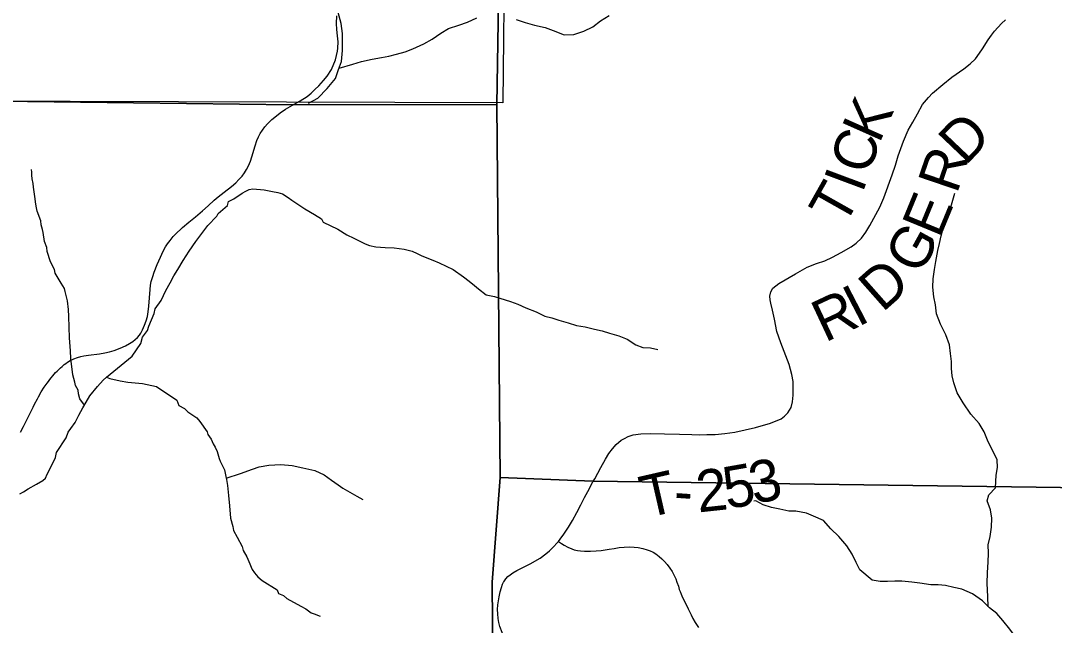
# Model space of a CAD drawing. Extents: x 0 to 34, y -8.9 to 22.
# Drawn here: x 27.543 to 28.944, y 16.605 to 17.424 of the extents above; entities that cross this region are included whole.
import ezdxf

# ---------------------------------------------------------------- set-up
doc = ezdxf.new("R2010")
doc.units = 0
for name, color, linetype in [('GM_X_Corporation', 7, 'Continuous'), ('GM_X_Minor_River', 7, 'Continuous'), ('GM_X_Township_Road', 7, 'Continuous'), ('GM_X_Township_Road_Text', 7, 'Continuous')]:
    doc.layers.add(name, color=color, linetype=linetype)

msp = doc.modelspace()

# ---------------------------------------------------------------- linework, layer by layer
at = {"layer": 'GM_X_Corporation'}
for points in [[(30.5167, 16.7663), (30.5167, 21.4), (28.2203, 21.4), (28.2198, 21.3092), (28.2124, 18.7899), (28.2124, 18.7889), (28.2011, 18.1006), (28.201, 18.0921), (28.1882, 17.3108), (28.1928, 16.8054), (28.3182, 16.8002), (29.5528, 16.7835), (30.4571, 16.7673)], [(28.2049, 18.3054), (28.2008, 17.7487), (28.1963, 17.3129), (27.17, 17.3161), (27.198, 18.314)], [(23.7167, 15.9913), (23.7167, 14.6), (28.1739, 14.6), (28.1809, 15.2987), (28.1918, 16.1509), (28.1846, 16.3341), (28.1817, 16.6637), (28.1928, 16.8054), (28.1882, 17.3108), (27.911, 17.3104), (27.4798, 17.3159), (27.0561, 17.3117), (26.7292, 17.3169), (26.394, 17.3229), (26.1361, 17.3278), (26.135, 17.3055), (26.1186, 15.9366), (25.7922, 15.939), (25.6785, 15.9418), (24.8268, 15.964), (24.2771, 15.9807), (24.0651, 15.9828)], [(28.1739, 14.6), (30.5167, 14.6), (30.5167, 16.7663), (30.4571, 16.7673), (29.5528, 16.7835), (28.3182, 16.8002), (28.1928, 16.8054), (28.1817, 16.6637), (28.1846, 16.3341), (28.1918, 16.1509), (28.1809, 15.2987)]]:
    msp.add_lwpolyline(points, close=True, dxfattribs=at)
for points in [[(26.1391, 17.8847), (26.1361, 17.3278), (26.394, 17.3229), (26.7292, 17.3169), (27.0561, 17.3117), (27.4798, 17.3159), (27.911, 17.3104), (28.1882, 17.3108), (28.201, 18.0921)], [(29.5528, 16.7835), (28.3182, 16.8002), (28.1928, 16.8054), (28.1882, 17.3108), (27.911, 17.3104), (27.4798, 17.3159), (27.0561, 17.3117), (26.7292, 17.3169), (26.394, 17.3229), (26.1361, 17.3278), (26.1391, 17.8847)], [(26.1391, 17.8847), (26.1361, 17.3278), (26.394, 17.3229), (26.7292, 17.3169), (27.0561, 17.3117), (27.4798, 17.3159), (27.911, 17.3104), (28.1882, 17.3108), (28.1928, 16.8054), (28.3182, 16.8002), (29.5528, 16.7835)]]:
    msp.add_lwpolyline(points, dxfattribs=at)
at = {"layer": 'GM_X_Minor_River'}
for points in [[(27.9331, 17.3125), (27.9454, 17.3194), (27.9581, 17.3325), (27.9693, 17.3459), (27.9737, 17.3582), (27.9777, 17.3688), (27.9791, 17.384), (27.9788, 17.4068), (27.9771, 17.4205), (27.9731, 17.4356)], [(28.2145, 17.4258), (28.2267, 17.4218), (28.2393, 17.4182), (28.2537, 17.4149), (28.2644, 17.4109), (28.2793, 17.405), (28.2925, 17.4056), (28.3061, 17.4103), (28.3182, 17.4162), (28.3287, 17.4243), (28.3404, 17.4313)], [(27.9745, 17.3602), (27.993, 17.3652), (28.0047, 17.3688), (28.0194, 17.372), (28.0319, 17.3745), (28.0418, 17.3761), (28.0523, 17.3789), (28.0641, 17.3821), (28.0743, 17.386), (28.0893, 17.3931), (28.1006, 17.3993), (28.1123, 17.4074), (28.1225, 17.4136), (28.1368, 17.4184), (28.1485, 17.4223), (28.161, 17.4282)], [(27.6291, 16.9033), (27.6229, 16.912), (27.6213, 16.9188), (27.6205, 16.9237), (27.6169, 16.9301), (27.6161, 16.9346), (27.6133, 16.9444), (27.6106, 16.9668), (27.6101, 16.977), (27.609, 16.9944), (27.6081, 17.0236), (27.6076, 17.033), (27.6062, 17.0447), (27.603, 17.0572), (27.6022, 17.0613), (27.5975, 17.0685), (27.5897, 17.082), (27.5885, 17.0872), (27.583, 17.0974), (27.5789, 17.1117), (27.5781, 17.117), (27.5753, 17.1249), (27.5732, 17.1374), (27.5724, 17.1412), (27.5704, 17.1476), (27.5699, 17.1532), (27.5651, 17.1664), (27.5639, 17.1732), (27.563, 17.1789), (27.5625, 17.183), (27.56, 17.1989), (27.5595, 17.2038), (27.5583, 17.2099), (27.5578, 17.2152), (27.5578, 17.219), (27.5573, 17.2227)], [(27.6601, 16.9409), (27.6592, 16.9411), (27.6939, 16.9698), (27.7057, 16.9867), (27.7078, 16.9954), (27.7145, 17.0046), (27.7163, 17.0104), (27.7239, 17.0275), (27.725, 17.034), (27.7331, 17.0451), (27.7397, 17.0589), (27.7452, 17.0689), (27.7503, 17.0784), (27.7559, 17.0872), (27.7632, 17.0995), (27.771, 17.1118), (27.7802, 17.1252), (27.7869, 17.134), (27.7965, 17.1467), (27.8088, 17.1595), (27.8106, 17.1629), (27.8229, 17.1737), (27.8243, 17.1794), (27.8315, 17.183), (27.8431, 17.1904), (27.8479, 17.1931), (27.8525, 17.1955), (27.8574, 17.1963), (27.8729, 17.1951), (27.8839, 17.193), (27.8912, 17.1916), (27.8976, 17.1895), (27.9053, 17.1847), (27.9103, 17.181), (27.9279, 17.1696), (27.9409, 17.1615), (27.9505, 17.1556), (27.9528, 17.1515), (27.9727, 17.142), (27.9849, 17.1342), (27.9945, 17.1295), (28.0018, 17.1258), (28.0098, 17.1218), (28.0155, 17.1196), (28.0242, 17.1179), (28.0367, 17.117), (28.0489, 17.1164), (28.0625, 17.1148), (28.0732, 17.1119), (28.0804, 17.1087), (28.0858, 17.1061), (28.0934, 17.1028), (28.1014, 17.0996), (28.1098, 17.0963), (28.1194, 17.0919), (28.1289, 17.0872), (28.1431, 17.0772), (28.1508, 17.0713), (28.1577, 17.0657), (28.1635, 17.0609), (28.1738, 17.0527), (28.1807, 17.0514), (28.1852, 17.0505)], [(28.8641, 16.7912), (28.8649, 16.8085), (28.8667, 16.8191), (28.8662, 16.8294), (28.8595, 16.8433), (28.8541, 16.8535), (28.8486, 16.8671), (28.842, 16.8784), (28.8305, 16.8912), (28.82, 16.9066), (28.8123, 16.9202), (28.8075, 16.9334), (28.8051, 16.9433), (28.8042, 16.9531), (28.8045, 16.9626), (28.8032, 16.9732), (28.8015, 16.985), (28.7968, 16.9986), (28.7894, 17.0129), (28.7843, 17.0269), (28.7826, 17.0394), (28.7806, 17.05), (28.7793, 17.0633), (28.7795, 17.0747), (28.7812, 17.0872), (28.783, 17.0979), (28.7858, 17.1131), (28.788, 17.1226), (28.7905, 17.1326), (28.7941, 17.1463), (28.7981, 17.1577), (28.8025, 17.1684), (28.8055, 17.1779), (28.8091, 17.1905)], [(28.1852, 17.0505), (28.2066, 17.0437), (28.2165, 17.0401), (28.2276, 17.0353), (28.2417, 17.0298), (28.2532, 17.0238), (28.2627, 17.0217), (28.2722, 17.0184), (28.2848, 17.0147), (28.2962, 17.0115), (28.308, 17.0094), (28.3205, 17.0065), (28.3308, 17.004), (28.3407, 17.001), (28.3537, 16.9974), (28.3647, 16.9926), (28.3766, 16.9852), (28.3861, 16.9815), (28.3964, 16.9809), (28.4063, 16.9787)], [(27.5418, 16.7832), (27.5467, 16.786), (27.5531, 16.7899), (27.5643, 16.7965), (27.573, 16.8012), (27.5763, 16.8043), (27.5789, 16.81), (27.5836, 16.8192), (27.5898, 16.8326), (27.5912, 16.8394), (27.6045, 16.859), (27.6071, 16.8666), (27.6108, 16.8716), (27.6167, 16.8797), (27.6214, 16.89), (27.6269, 16.8996), (27.6317, 16.9076), (27.6365, 16.9161), (27.6469, 16.9288), (27.6547, 16.9372), (27.6592, 16.9411), (27.6637, 16.9397), (27.6778, 16.9365), (27.6881, 16.9344), (27.7078, 16.9325), (27.7268, 16.9287), (27.7544, 16.9099), (27.7572, 16.9031), (27.7648, 16.8987), (27.7694, 16.8942), (27.7817, 16.8861), (27.7856, 16.8812), (27.7957, 16.8674), (27.7965, 16.8636), (27.8008, 16.8573), (27.8039, 16.8509), (27.8062, 16.8464), (27.809, 16.8407), (27.8118, 16.8313), (27.8134, 16.8275), (27.8189, 16.8155), (27.8209, 16.8065), (27.8218, 16.8027), (27.8231, 16.7944), (27.8244, 16.7811), (27.8258, 16.7668), (27.8272, 16.7501), (27.8305, 16.7388), (27.8313, 16.7335), (27.8364, 16.7245), (27.843, 16.7117), (27.8443, 16.7065), (27.8493, 16.6978), (27.8533, 16.6884), (27.8553, 16.6839), (27.8565, 16.6805), (27.8599, 16.676), (27.8642, 16.6708), (27.87, 16.6656), (27.8903, 16.6531), (27.8922, 16.6482), (27.8991, 16.6453), (27.9037, 16.6412), (27.9225, 16.6309), (27.9293, 16.6273), (27.9366, 16.6221), (27.9408, 16.6207), (27.9485, 16.6174)], [(27.8214, 16.8044), (27.8409, 16.8106), (27.8571, 16.8166), (27.8662, 16.8198), (27.879, 16.8219), (27.8953, 16.823), (27.9108, 16.8214), (27.9253, 16.8186), (27.9416, 16.8147), (27.9542, 16.8089), (27.9642, 16.8019), (27.973, 16.7956), (27.9795, 16.7908), (27.9983, 16.7801), (28.0067, 16.7753)], [(28.8543, 16.6303), (28.8536, 16.6443), (28.8529, 16.6618), (28.8531, 16.6766), (28.8541, 16.6906), (28.8546, 16.7028), (28.8543, 16.7142), (28.8567, 16.7255), (28.8584, 16.738), (28.8589, 16.7502), (28.8571, 16.7617), (28.8527, 16.7736), (28.8552, 16.7817), (28.8641, 16.7912)], [(28.7763, 16.6601), (28.7616, 16.6623), (28.7506, 16.6635), (28.7373, 16.6649), (28.7278, 16.6649), (28.7175, 16.6642), (28.7076, 16.6642), (28.697, 16.6662), (28.6801, 16.6803), (28.6752, 16.69), (28.6696, 16.7016), (28.6625, 16.7126), (28.6516, 16.7252), (28.641, 16.736), (28.6308, 16.7471), (28.6174, 16.753), (28.6077, 16.7568), (28.5933, 16.7597), (28.5838, 16.7597), (28.5718, 16.7625), (28.5604, 16.7645), (28.5492, 16.7685), (28.5391, 16.7735), (28.5364, 16.7732)], [(28.9478, 16.4515), (28.9393, 16.4652), (28.9305, 16.4823), (28.9275, 16.4935), (28.9261, 16.5053), (28.9244, 16.5179), (28.9206, 16.5284), (28.9147, 16.5404), (28.9098, 16.5517), (28.9051, 16.5652), (28.8977, 16.58), (28.8909, 16.5898), (28.8834, 16.6), (28.8739, 16.6114), (28.866, 16.6209), (28.8557, 16.6289), (28.8462, 16.6381), (28.8329, 16.6478), (28.8183, 16.6538), (28.8077, 16.6565), (28.7964, 16.6589), (28.7862, 16.6597), (28.7763, 16.6601)]]:
    msp.add_lwpolyline(points, dxfattribs=at)
at = {"layer": 'GM_X_Township_Road'}
for points in [[(27.9112, 17.3099), (27.9215, 17.3157), (27.9311, 17.3218), (27.9365, 17.326), (27.9417, 17.3309), (27.9468, 17.3361), (27.9531, 17.3433), (27.958, 17.3491), (27.9641, 17.3582), (27.9695, 17.3711), (27.9722, 17.3828), (27.9727, 17.3869), (27.9731, 17.3956), (27.9724, 17.4036), (27.9711, 17.4122), (27.9707, 17.4207), (27.9712, 17.4307)], [(28.3184, 16.7996), (28.321, 16.8035), (28.329, 16.8189), (28.3354, 16.8304), (28.3399, 16.8378), (28.3449, 16.8443), (28.3501, 16.85), (28.3568, 16.8557), (28.3613, 16.8584), (28.366, 16.8608), (28.3731, 16.863), (28.3835, 16.8647), (28.397, 16.8651), (28.4155, 16.8644), (28.4359, 16.8642), (28.4526, 16.8634), (28.4635, 16.8632), (28.473, 16.8634), (28.484, 16.8637), (28.497, 16.8651), (28.5107, 16.8669), (28.5248, 16.87), (28.5389, 16.8732), (28.5592, 16.8788), (28.5734, 16.8847), (28.5781, 16.8883), (28.5824, 16.8928), (28.5871, 16.9), (28.5889, 16.9078), (28.5898, 16.9169), (28.5898, 16.9249), (28.5896, 16.9354), (28.5882, 16.9447), (28.5843, 16.9586), (28.5732, 16.9876), (28.5678, 17.003), (28.5645, 17.02), (28.5618, 17.032), (28.5595, 17.0415), (28.5586, 17.0461), (28.5581, 17.0511), (28.5594, 17.0568), (28.5621, 17.0618), (28.5702, 17.068), (28.593, 17.0815), (28.609, 17.0902), (28.6216, 17.0951), (28.6325, 17.0991), (28.6431, 17.1039), (28.6549, 17.1102), (28.6682, 17.1177), (28.6753, 17.1229), (28.6822, 17.1297), (28.6881, 17.1376), (28.6938, 17.1469), (28.7073, 17.1716), (28.7126, 17.1845), (28.7238, 17.2153), (28.7286, 17.2286), (28.7322, 17.2414), (28.7392, 17.2611), (28.7458, 17.2759), (28.7518, 17.2869), (28.7581, 17.298), (28.7649, 17.3107), (28.7731, 17.3204), (28.7788, 17.3261), (28.7927, 17.338), (28.8049, 17.3476), (28.8209, 17.3589), (28.8295, 17.3658), (28.8368, 17.3728), (28.8424, 17.3802), (28.8466, 17.3863), (28.8541, 17.3984), (28.8584, 17.4049), (28.8626, 17.4103), (28.872, 17.4206), (28.8777, 17.4253)], [(27.5427, 16.8667), (27.5466, 16.8743), (27.55, 16.8809), (27.5595, 16.9005), (27.5617, 16.9049), (27.5654, 16.9121), (27.5669, 16.9148), (27.5706, 16.9213), (27.5746, 16.9276), (27.5786, 16.9331), (27.5804, 16.9356), (27.5822, 16.9381), (27.584, 16.9404), (27.5865, 16.9433), (27.5883, 16.9455), (27.5902, 16.9474), (27.5923, 16.9495), (27.5944, 16.9518), (27.5967, 16.9538), (27.599, 16.9559), (27.6018, 16.9583), (27.6038, 16.9598), (27.6062, 16.9616), (27.61, 16.9637), (27.615, 16.9662), (27.6196, 16.968), (27.6244, 16.9695), (27.6286, 16.9704), (27.6348, 16.9713), (27.6496, 16.973), (27.6569, 16.9742), (27.663, 16.9757), (27.6695, 16.9776), (27.6776, 16.9807), (27.685, 16.9839), (27.6905, 16.9868), (27.6947, 16.9895), (27.6981, 16.9921), (27.7013, 16.9952), (27.7037, 16.998), (27.7058, 17.0011), (27.7081, 17.0055), (27.7108, 17.0117), (27.7129, 17.0176), (27.7145, 17.0236), (27.7156, 17.0296), (27.7166, 17.0377), (27.7174, 17.0488), (27.7181, 17.06), (27.7189, 17.0661), (27.7198, 17.071), (27.7217, 17.0776), (27.7236, 17.0834), (27.7277, 17.0938), (27.7321, 17.1041), (27.7358, 17.1119), (27.7392, 17.1179), (27.7419, 17.1221), (27.7453, 17.1265), (27.7497, 17.1317), (27.7544, 17.1367), (27.7597, 17.1419), (27.762, 17.144), (27.7705, 17.1511), (27.7798, 17.1584), (27.7892, 17.1665), (27.797, 17.1736), (27.8052, 17.1812), (27.8104, 17.1856), (27.8187, 17.1921), (27.8286, 17.1997), (27.8342, 17.2045), (27.8387, 17.2089), (27.8428, 17.2136), (27.8461, 17.2181), (27.849, 17.2228), (27.8515, 17.2278), (27.8541, 17.2341), (27.8561, 17.24), (27.8604, 17.2549), (27.8628, 17.2619), (27.865, 17.2671), (27.8674, 17.2715), (27.8704, 17.2761), (27.8738, 17.2806), (27.8775, 17.2847), (27.8834, 17.2903), (27.8895, 17.2956), (27.8944, 17.2994), (27.9016, 17.3043), (27.9112, 17.3099)], [(28.2717, 16.7188), (28.2742, 16.7219), (28.279, 16.7284), (28.2854, 16.7381), (28.2908, 16.747), (28.2968, 16.7577), (28.3021, 16.7681), (28.3071, 16.7781), (28.3113, 16.7864), (28.3184, 16.7996)], [(28.1968, 16.6625), (28.1973, 16.6635), (28.1976, 16.6641), (28.2004, 16.6681), (28.2032, 16.671), (28.2061, 16.6735), (28.21, 16.6761), (28.2154, 16.6792), (28.2232, 16.6834), (28.2333, 16.6884), (28.2468, 16.6962), (28.2547, 16.7018), (28.2595, 16.7061), (28.2648, 16.7113), (28.2699, 16.7167), (28.2717, 16.7188)], [(28.2717, 16.7188), (28.2759, 16.716), (28.2795, 16.7137), (28.2843, 16.7111), (28.2898, 16.7087), (28.2932, 16.7074), (28.2974, 16.7064), (28.3017, 16.7058), (28.3072, 16.7055), (28.3153, 16.7055), (28.3227, 16.7058), (28.3295, 16.7065), (28.3406, 16.7081), (28.3473, 16.7093), (28.3541, 16.7103), (28.3608, 16.711), (28.3676, 16.7112), (28.3744, 16.7109), (28.3799, 16.7103), (28.386, 16.7091), (28.392, 16.7075), (28.396, 16.706), (28.3999, 16.7041), (28.4036, 16.7018), (28.4081, 16.6985), (28.4119, 16.6953), (28.4153, 16.6917), (28.4189, 16.6875), (28.4226, 16.6825), (28.4256, 16.6779), (28.4286, 16.6726), (28.4306, 16.6682), (28.4323, 16.6636), (28.4342, 16.6579), (28.4355, 16.6537), (28.4365, 16.6508), (28.4379, 16.6473), (28.4388, 16.645), (28.442, 16.6383), (28.4437, 16.635), (28.4476, 16.6272), (28.4514, 16.6194), (28.4538, 16.6144), (28.4569, 16.609), (28.4613, 16.6022)], [(28.1973, 16.5889), (28.197, 16.5899), (28.1968, 16.5905), (28.1952, 16.5952), (28.1924, 16.6034), (28.1909, 16.6088), (28.1899, 16.6143), (28.1893, 16.6204), (28.1892, 16.6266), (28.1896, 16.6328), (28.1902, 16.6383), (28.1912, 16.6436), (28.1927, 16.6502), (28.1943, 16.6562), (28.1959, 16.6606), (28.1968, 16.6625)]]:
    msp.add_lwpolyline(points, dxfattribs=at)

# ---------------------------------------------------------------- texts
at = {"layer": 'GM_X_Township_Road_Text'}
for s, rotation, p in [('K', 66.026, (28.7064, 17.2567)), ('D', 46.3679, (28.8233, 17.227)), ('C', 71.9979, (28.6925, 17.2138)), ('R', 71.2281, (28.8116, 17.1884)), ('I', 69.5138, (28.6835, 17.1894)), ('T', 60.5916, (28.6585, 17.1436)), ('E', 67.5914, (28.7884, 17.1279)), ('G', 61.2786, (28.7614, 17.0779)), ('D', 41.5116, (28.7107, 17.0281)), ('I', 27.4269, (28.6775, 17.0087)), ('R', 25.0864, (28.6329, 16.9878)), ('3', 12.3046, (28.537, 16.7688)), ('T', 12.9011, (28.39, 16.7501)), ('2', 6.1608, (28.4612, 16.7579)), ('5', 10.0444, (28.5001, 16.7623)), ('-', 356.1018, (28.427, 16.7593))]:
    msp.add_text(s, height=0.0568, rotation=rotation, dxfattribs=at).set_placement(p)

doc.saveas('drawing.dxf')
